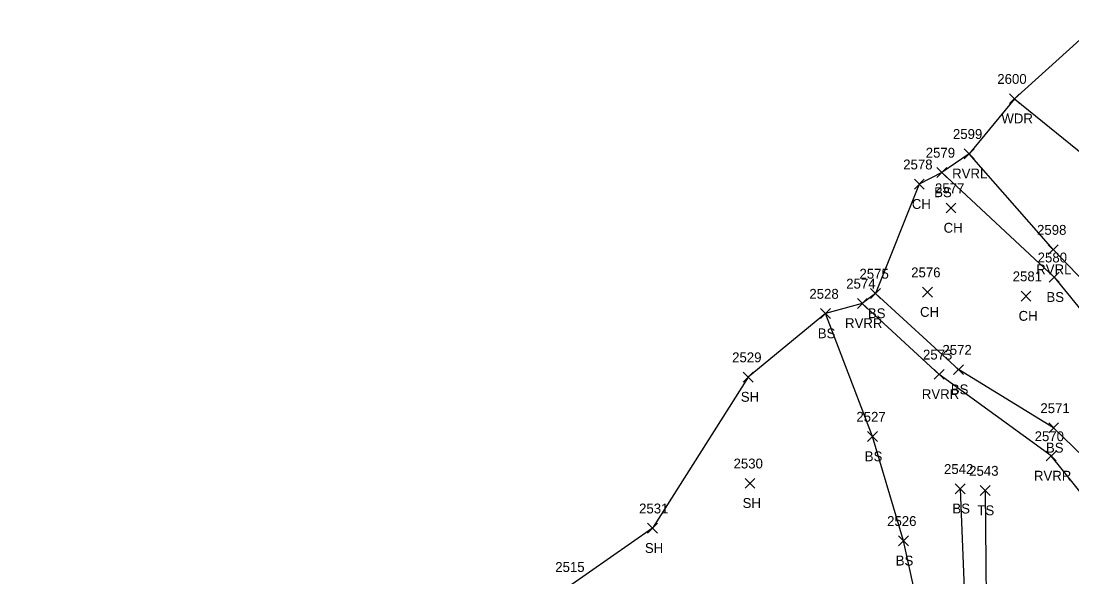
# Model space of a CAD drawing. Extents: x 1633660 to 1636532, y 388643 to 392631.
# Drawn here: x 1634455.1 to 1634668.1, y 389289.2 to 389401.8 of the extents above; entities that cross this region are included whole.
import ezdxf

# ---------------------------------------------------------------- set-up
doc = ezdxf.new("R2010")
doc.units = 0
for name, color, linetype in [('L_A', 7, 'Continuous'), ('L_I', 7, 'Continuous'), ('L_TIC', 7, 'Continuous'), ('LAWA', 7, 'Continuous'), ('LAWE', 7, 'Continuous'), ('LELB', 7, 'Continuous'), ('LSOGP', 7, 'Continuous')]:
    doc.layers.add(name, color=color, linetype=linetype)

msp = doc.modelspace()

# ---------------------------------------------------------------- linework, layer by layer
at = {"layer": 'L_TIC'}
for points in [[(1634655.41, 389385.08), (1634657.41, 389387.08)], [(1634657.41, 389385.08), (1634655.41, 389387.08)], [(1634646.22, 389373.92), (1634648.22, 389375.92)], [(1634648.22, 389373.92), (1634646.22, 389375.92)], [(1634640.71, 389370.13), (1634642.71, 389372.13)], [(1634642.71, 389370.13), (1634640.71, 389372.13)], [(1634636.13, 389367.75), (1634638.13, 389369.75)], [(1634638.13, 389367.75), (1634636.13, 389369.75)], [(1634642.57, 389362.93), (1634644.57, 389364.93)], [(1634644.57, 389362.93), (1634642.57, 389364.93)], [(1634663.26, 389354.51), (1634665.26, 389356.51)], [(1634665.26, 389354.51), (1634663.26, 389356.51)], [(1634663.46, 389348.91), (1634665.46, 389350.91)], [(1634665.46, 389348.91), (1634663.46, 389350.91)], [(1634627.27, 389345.62), (1634629.27, 389347.62)], [(1634629.27, 389345.62), (1634627.27, 389347.62)], [(1634637.8, 389345.89), (1634639.8, 389347.89)], [(1634639.8, 389345.89), (1634637.8, 389347.89)], [(1634624.58, 389343.61), (1634626.58, 389345.61)], [(1634626.58, 389343.61), (1634624.58, 389345.61)], [(1634657.76, 389345.09), (1634659.76, 389347.09)], [(1634659.76, 389345.09), (1634657.76, 389347.09)], [(1634617.12, 389341.55), (1634619.12, 389343.55)], [(1634619.12, 389341.55), (1634617.12, 389343.55)], [(1634601.47, 389328.69), (1634603.47, 389330.69)], [(1634603.47, 389328.69), (1634601.47, 389330.69)], [(1634640.14, 389329.24), (1634642.14, 389331.24)], [(1634642.14, 389329.24), (1634640.14, 389331.24)], [(1634644.08, 389330.2), (1634646.08, 389332.2)], [(1634646.08, 389330.2), (1634644.08, 389332.2)], [(1634663.36, 389318.39), (1634665.36, 389320.39)], [(1634665.36, 389318.39), (1634663.36, 389320.39)], [(1634626.64, 389316.64), (1634628.64, 389318.64)], [(1634628.64, 389316.64), (1634626.64, 389318.64)], [(1634662.85, 389312.71), (1634664.85, 389314.71)], [(1634664.85, 389312.71), (1634662.85, 389314.71)], [(1634601.84, 389307.18), (1634603.84, 389309.18)], [(1634603.84, 389307.18), (1634601.84, 389309.18)], [(1634644.4, 389306.06), (1634646.4, 389308.06)], [(1634646.4, 389306.06), (1634644.4, 389308.06)], [(1634649.5, 389305.7), (1634651.5, 389307.7)], [(1634651.5, 389305.7), (1634649.5, 389307.7)], [(1634582.05, 389298.07), (1634584.05, 389300.07)], [(1634584.05, 389298.07), (1634582.05, 389300.07)], [(1634632.92, 389295.52), (1634634.92, 389297.52)], [(1634634.92, 389295.52), (1634632.92, 389297.52)]]:
    msp.add_lwpolyline(points, dxfattribs=at)
at = {"layer": 'LAWA'}
msp.add_lwpolyline([(1634656.41, 389386.08), (1634684.77, 389363.07), (1634708.79, 389342.88), (1634727.74, 389312.62), (1634749.11, 389283.63)], dxfattribs=at)
at = {"layer": 'LAWE'}
for points in [[(1634748.89, 389270.78), (1634735.19, 389280.87), (1634720.26, 389300.16), (1634697.78, 389320.61), (1634664.26, 389355.51), (1634647.22, 389374.92)], [(1634726.75, 389249.59), (1634713.25, 389262.22), (1634694.91, 389274.92), (1634673.59, 389301.63), (1634663.85, 389313.71), (1634641.14, 389330.24), (1634625.58, 389344.61)]]:
    msp.add_lwpolyline(points, dxfattribs=at)
at = {"layer": 'LELB'}
for points in [[(1634641.71, 389371.13), (1634664.46, 389349.91), (1634678.27, 389333.06), (1634696, 389315.41), (1634713, 389296.84), (1634727.52, 389281.42), (1634745.22, 389266.89), (1634752.92, 389261.93)], [(1634742.97, 389244.48), (1634736.28, 389256.06), (1634722.01, 389268.8), (1634707.38, 389278.77), (1634697.7, 389284.25), (1634680.66, 389303.58), (1634664.36, 389319.39), (1634645.08, 389331.2), (1634628.27, 389346.62)], [(1634627.22, 389219.99), (1634633.29, 389233.17), (1634641.58, 389261.92), (1634633.92, 389296.52), (1634627.64, 389317.64), (1634618.12, 389342.55)], [(1634645.4, 389307.06), (1634646.96, 389268.22), (1634654.85, 389241.93), (1634647.98, 389239.44), (1634643.89, 389254.71)], [(1634650.5, 389306.7), (1634650.82, 389269.82), (1634662.74, 389235.25), (1634646.56, 389225.22), (1634640.19, 389246.09)]]:
    msp.add_lwpolyline(points, dxfattribs=at)
at = {"layer": 'LSOGP'}
msp.add_lwpolyline([(1634673.84, 389401.81), (1634656.41, 389386.08), (1634647.22, 389374.92), (1634641.71, 389371.13), (1634637.13, 389368.75), (1634628.27, 389346.62), (1634625.58, 389344.61), (1634618.12, 389342.55), (1634602.47, 389329.69), (1634583.05, 389299.07), (1634566.05, 389287.22), (1634558.9, 389281.65), (1634537.12, 389267.57), (1634504.95, 389250.1), (1634474.13, 389224.17), (1634424.09, 389193.65)], dxfattribs=at)

# ---------------------------------------------------------------- texts
at = {"layer": 'L_A'}
for s, p in [('WDR', (1634653.77, 389381.08)), ('RVRL', (1634643.79, 389369.92)), ('BS', (1634640.15, 389366.13)), ('CH', (1634635.62, 389363.75)), ('CH', (1634642.06, 389358.93)), ('RVRL', (1634660.83, 389350.51)), ('BS', (1634662.9, 389344.91)), ('BS', (1634626.71, 389341.62)), ('CH', (1634637.29, 389341.89)), ('RVRR', (1634622.09, 389339.61)), ('CH', (1634657.25, 389341.09)), ('BS', (1634616.56, 389337.55)), ('SH', (1634600.96, 389324.69)), ('RVRR', (1634637.65, 389325.24)), ('BS', (1634643.52, 389326.2)), ('BS', (1634662.8, 389314.39)), ('BS', (1634626.08, 389312.64)), ('RVRR', (1634660.37, 389308.71)), ('SH', (1634601.33, 389303.18)), ('BS', (1634643.84, 389302.06)), ('TS', (1634648.91, 389301.7)), ('SH', (1634581.53, 389294.07)), ('BS', (1634632.36, 389291.52))]:
    msp.add_text(s, height=2, dxfattribs=at).set_placement(p)
at = {"layer": 'L_I'}
for s, p in [('2600', (1634652.94, 389389.08)), ('2599', (1634643.95, 389377.92)), ('2579', (1634638.44, 389374.13)), ('2578', (1634633.87, 389371.75)), ('2577', (1634640.31, 389366.93)), ('2598', (1634661, 389358.51)), ('2580', (1634661.12, 389352.91)), ('2576', (1634635.49, 389349.89)), ('2574', (1634622.32, 389347.61)), ('2575', (1634625.01, 389349.62)), ('2581', (1634656.06, 389349.09)), ('2528', (1634614.86, 389345.55)), ('2529', (1634599.21, 389332.69)), ('2573', (1634637.88, 389333.24)), ('2572', (1634641.82, 389334.2)), ('2571', (1634661.67, 389322.39)), ('2527', (1634624.38, 389320.64)), ('2570', (1634660.51, 389316.71)), ('2530', (1634599.49, 389311.18)), ('2542', (1634642.14, 389310.06)), ('2543', (1634647.24, 389309.7)), ('2531', (1634580.35, 389302.07)), ('2526', (1634630.61, 389299.52)), ('2515', (1634563.36, 389290.22))]:
    msp.add_text(s, height=2, dxfattribs=at).set_placement(p)

doc.saveas('drawing.dxf')
